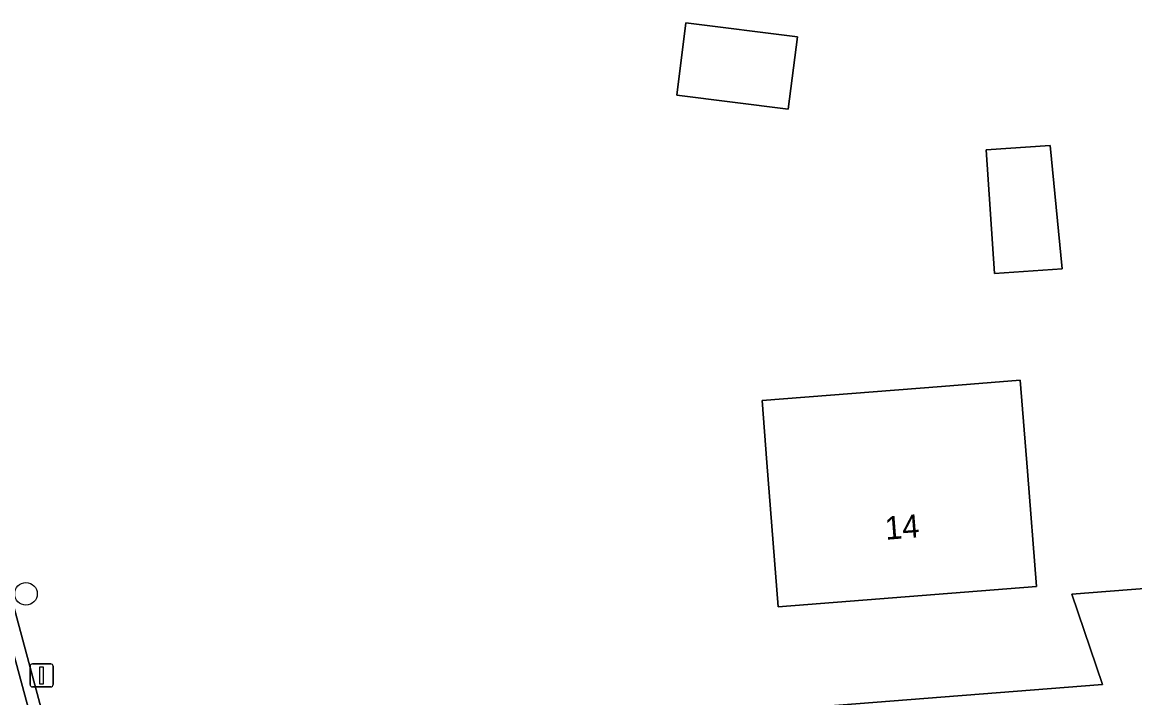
# Model space of a CAD drawing. Extents: x 162661 to 163484, y 380247 to 381230.
# Drawn here: x 162908.64 to 162956.75, y 380433.93 to 380463.16 of the extents above; entities that cross this region are included whole.
import ezdxf

# ---------------------------------------------------------------- set-up
doc = ezdxf.new("R2010")
doc.units = 0
for name, color, linetype in [('IMGEO_Boom', 7, 'Continuous'), ('IMGEO_Erf', 7, 'Continuous'), ('IMGEO_Lichtmast', 7, 'Continuous'), ('IMGEO_Pand', 7, 'Continuous'), ('IMGEO_Pand_nummerreeks', 7, 'Continuous'), ('IMGEO_Rijbaan_lokaal_gesloten', 7, 'Continuous'), ('IMGEO_Rijbaan_lokaal_open', 7, 'Continuous'), ('IMGEO_Voetpad_open', 7, 'Continuous')]:
    doc.layers.add(name, color=color, linetype=linetype)

msp = doc.modelspace()

# ---------------------------------------------------------------- linework, layer by layer
at = {"layer": 'IMGEO_Boom'}
msp.add_circle((162908.804, 380438.433), 0.489, dxfattribs=at)
at = {"layer": 'IMGEO_Erf'}
msp.add_lwpolyline([(162947.904, 380489.571), (162929.546, 380483.194), (162909.571, 380476.241), (162906.797, 380475.275), (162901.101, 380473.756), (162901.068, 380473.747), (162901.759, 380471.365), (162899.45, 380470.72), (162899.457, 380470.696), (162910.123, 380431.006), (162913.618, 380431.232), (162955.354, 380434.5), (162954.04, 380438.409), (162989.976, 380441.225), (162989.708, 380445.324), (162996.691, 380445.849), (163000, 380446.098), (163035.591, 380448.726), (163040.495, 380449.119), (163037.069, 380497.617)], dxfattribs=at)
for points in [[(162942.164, 380462.528), (162941.769, 380459.4), (162936.945, 380460.008), (162937.34, 380463.137)], [(162953.614, 380452.485), (162950.691, 380452.287), (162950.33, 380457.632), (162953.098, 380457.82)], [(162952.11, 380443.734), (162952.501, 380438.749), (162941.335, 380437.874), (162940.847, 380444.105), (162940.636, 380446.795), (162948.394, 380447.403), (162951.802, 380447.67)]]:
    msp.add_lwpolyline(points, close=True, dxfattribs=at)
at = {"layer": 'IMGEO_Lichtmast'}
for p, q in [((162908.984, 380434.501), (162908.984, 380435.301)), ((162908.984, 380435.301), (162908.984, 380434.501)), ((162909.084, 380435.401), (162909.874, 380435.401)), ((162909.874, 380435.401), (162909.084, 380435.401)), ((162909.974, 380435.301), (162909.974, 380434.501)), ((162909.974, 380434.501), (162909.974, 380435.301)), ((162909.874, 380434.401), (162909.084, 380434.401)), ((162909.084, 380434.401), (162909.874, 380434.401))]:
    msp.add_line(p, q, dxfattribs=at)
msp.add_lwpolyline([(162909.404, 380435.276), (162909.554, 380435.276), (162909.554, 380434.526), (162909.404, 380434.526), (162909.404, 380435.276)], dxfattribs=at)
for centre, start, end in [((162909.084, 380435.301), 90, 180), ((162909.084, 380435.301), 90, 180), ((162909.874, 380435.301), 0, 90), ((162909.874, 380435.301), 360, 90), ((162909.084, 380434.501), 180, 270), ((162909.084, 380434.501), 180, 270), ((162909.874, 380434.501), 270, 0), ((162909.874, 380434.501), 270, 0)]:
    msp.add_arc(centre, 0.1, start, end, dxfattribs=at)
at = {"layer": 'IMGEO_Pand'}
for points in [[(162936.945, 380460.008), (162941.769, 380459.4), (162942.164, 380462.528), (162937.34, 380463.137)], [(162953.614, 380452.485), (162953.098, 380457.82), (162950.33, 380457.632), (162950.691, 380452.287)], [(162948.394, 380447.403), (162940.636, 380446.795), (162940.847, 380444.105), (162941.335, 380437.874), (162952.501, 380438.749), (162952.11, 380443.734), (162951.802, 380447.67)]]:
    msp.add_lwpolyline(points, close=True, dxfattribs=at)
at = {"layer": 'IMGEO_Rijbaan_lokaal_gesloten'}
msp.add_lwpolyline([(162910.756, 380426.613), (162891.908, 380496.458)], dxfattribs=at)
at = {"layer": 'IMGEO_Rijbaan_lokaal_open'}
for points in [[(162891.908, 380496.458), (162910.756, 380426.613)], [(162911.251, 380426.767), (162910.685, 380428.926), (162910.123, 380431.006), (162899.457, 380470.696), (162899.45, 380470.72), (162898.766, 380473.128), (162897.817, 380476.62), (162894.653, 380488.389)]]:
    msp.add_lwpolyline(points, dxfattribs=at)
at = {"layer": 'IMGEO_Voetpad_open'}
msp.add_lwpolyline([(162989.976, 380441.225), (162954.04, 380438.409), (162955.354, 380434.5), (162913.618, 380431.232), (162910.123, 380431.006), (162910.685, 380428.926), (162916.963, 380429.245), (162955.782, 380432.288), (162956.344, 380428.909), (162959.369, 380429.435)], dxfattribs=at)

# ---------------------------------------------------------------- texts
at = {"layer": 'IMGEO_Pand_nummerreeks'}
msp.add_text('14', height=1, rotation=4.4809, dxfattribs=at).set_placement((162945.988, 380440.766))

doc.saveas('drawing.dxf')
